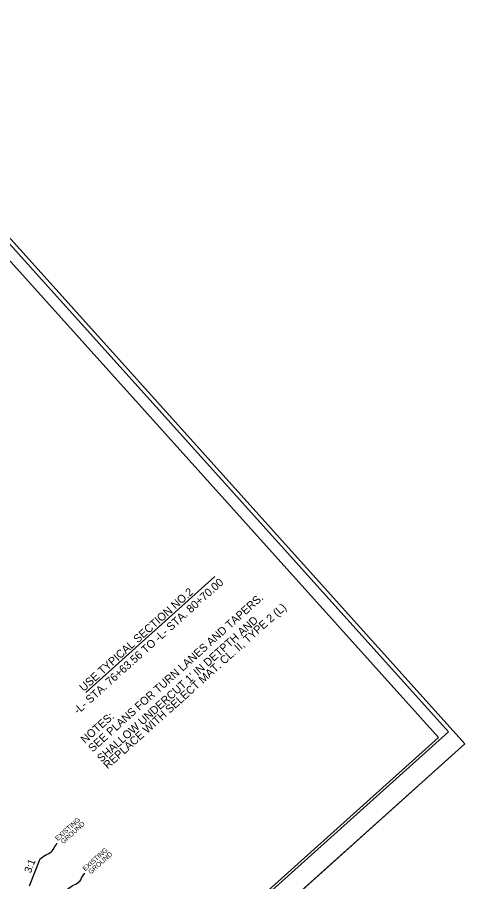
# Model space of a CAD drawing. Extents: x 2488411 to 2488707, y 383669 to 383962.
# Drawn here: x 2488647.1 to 2488707.5, y 383844.8 to 383961.6 of the extents above; entities that cross this region are included whole.
import ezdxf

# ---------------------------------------------------------------- set-up
doc = ezdxf.new("R2010")
doc.units = 0
for name, color, linetype in [('Old_Level_19', 7, 'Continuous'), ('Old_Level_21', 7, 'Continuous'), ('Prop Roadway Profile Bench Mark Info Text', 7, 'Continuous'), ('Prop XS SE Text', 7, 'Continuous'), ('Sheet Cutting Line CELL', 7, 'Continuous'), ('Sheet Plan CELL', 7, 'Continuous'), ('Sheet Title CELL', 7, 'Continuous'), ('Typical Text ID Circle CELL', 7, 'Continuous')]:
    doc.layers.add(name, color=color, linetype=linetype)

msp = doc.modelspace()

# ---------------------------------------------------------------- linework, layer by layer
at = {"layer": 'Old_Level_19'}
msp.add_lwpolyline([(2488619.23, 383961.6), (2488468.95, 383826.51), (2488557.19, 383728.34), (2488707.48, 383863.44)], close=True, dxfattribs=at)
at = {"layer": 'Old_Level_21'}
msp.add_lwpolyline([(2488620.63, 383959.24), (2488471.91, 383825.55), (2488556.55, 383731.39), (2488705.27, 383865.08)], close=True, dxfattribs=at)
at = {"layer": 'Prop XS SE Text'}
msp.add_line((2488557.19, 383728.34), (2488707.48, 383863.44), dxfattribs=at)
at = {"layer": 'Sheet Cutting Line CELL'}
msp.add_lwpolyline([(2488619.72, 383958.01), (2488485.86, 383837.67), (2488570.09, 383743.97), (2488703.95, 383864.31)], close=True, dxfattribs=at)
at = {"layer": 'Sheet Plan CELL'}
msp.add_line((2488650.13, 383847.86), (2488648.69, 383844.2), dxfattribs=at)
at = {"layer": 'Sheet Title CELL'}
msp.add_line((2488656.36, 383870.4), (2488673.77, 383886.05), dxfattribs=at)
at = {"layer": 'Typical Text ID Circle CELL'}
for points in [[(2488650.13, 383847.86), (2488650.36, 383848.07), (2488650.59, 383848.23), (2488650.81, 383848.38), (2488651.06, 383848.49), (2488651.26, 383848.58), (2488651.48, 383848.71), (2488651.66, 383848.84), (2488651.82, 383848.98), (2488651.98, 383849.22), (2488652.06, 383849.44), (2488652.2, 383849.61), (2488652.33, 383849.82), (2488652.49, 383850.06)], [(2488653.85, 383843.77), (2488654.08, 383843.98), (2488654.31, 383844.14), (2488654.53, 383844.29), (2488654.78, 383844.4), (2488654.98, 383844.48), (2488655.2, 383844.61), (2488655.38, 383844.75), (2488655.53, 383844.89), (2488655.7, 383845.13), (2488655.78, 383845.34), (2488655.91, 383845.51), (2488656.05, 383845.73), (2488656.21, 383845.96)]]:
    msp.add_lwpolyline(points, dxfattribs=at)

# ---------------------------------------------------------------- texts
at = {"layer": 'Prop Roadway Profile Bench Mark Info Text'}
msp.add_text('3:1', height=1, rotation=69.3909, dxfattribs=at).set_placement((2488648.93, 383845.91))
at = {"layer": 'Sheet Title CELL'}
for s, height, p in [('-L- STA. 76+63.56 TO -L- STA. 80+70.00', 1.0817, (2488655.3, 383867.38)), ('USE TYPICAL SECTION NO.2', 1.0817, (2488656.07, 383870.45)), ('SEE PLANS FOR TURN LANES AND TAPERS.', 1.0817, (2488657.27, 383862.27)), ('REPLACE WITH SELECT MAT. CL. II, TYPE 2 (L)', 1.0817, (2488659.3, 383859.98)), ("SHALLOW UNDERCUT 1' IN DETPTH AND ", 1.0817, (2488658.45, 383860.9)), ('NOTES:', 1.082, (2488656.25, 383863.42)), ('EXISTING', 0.65, (2488652.55, 383850.3)), ('GROUND', 0.65, (2488653.32, 383849.88)), ('EXISTING', 0.65, (2488656.26, 383846.2)), ('GROUND', 0.65, (2488657.03, 383845.79))]:
    msp.add_text(s, height=height, rotation=41.9538, dxfattribs=at).set_placement(p)

doc.saveas('drawing.dxf')
